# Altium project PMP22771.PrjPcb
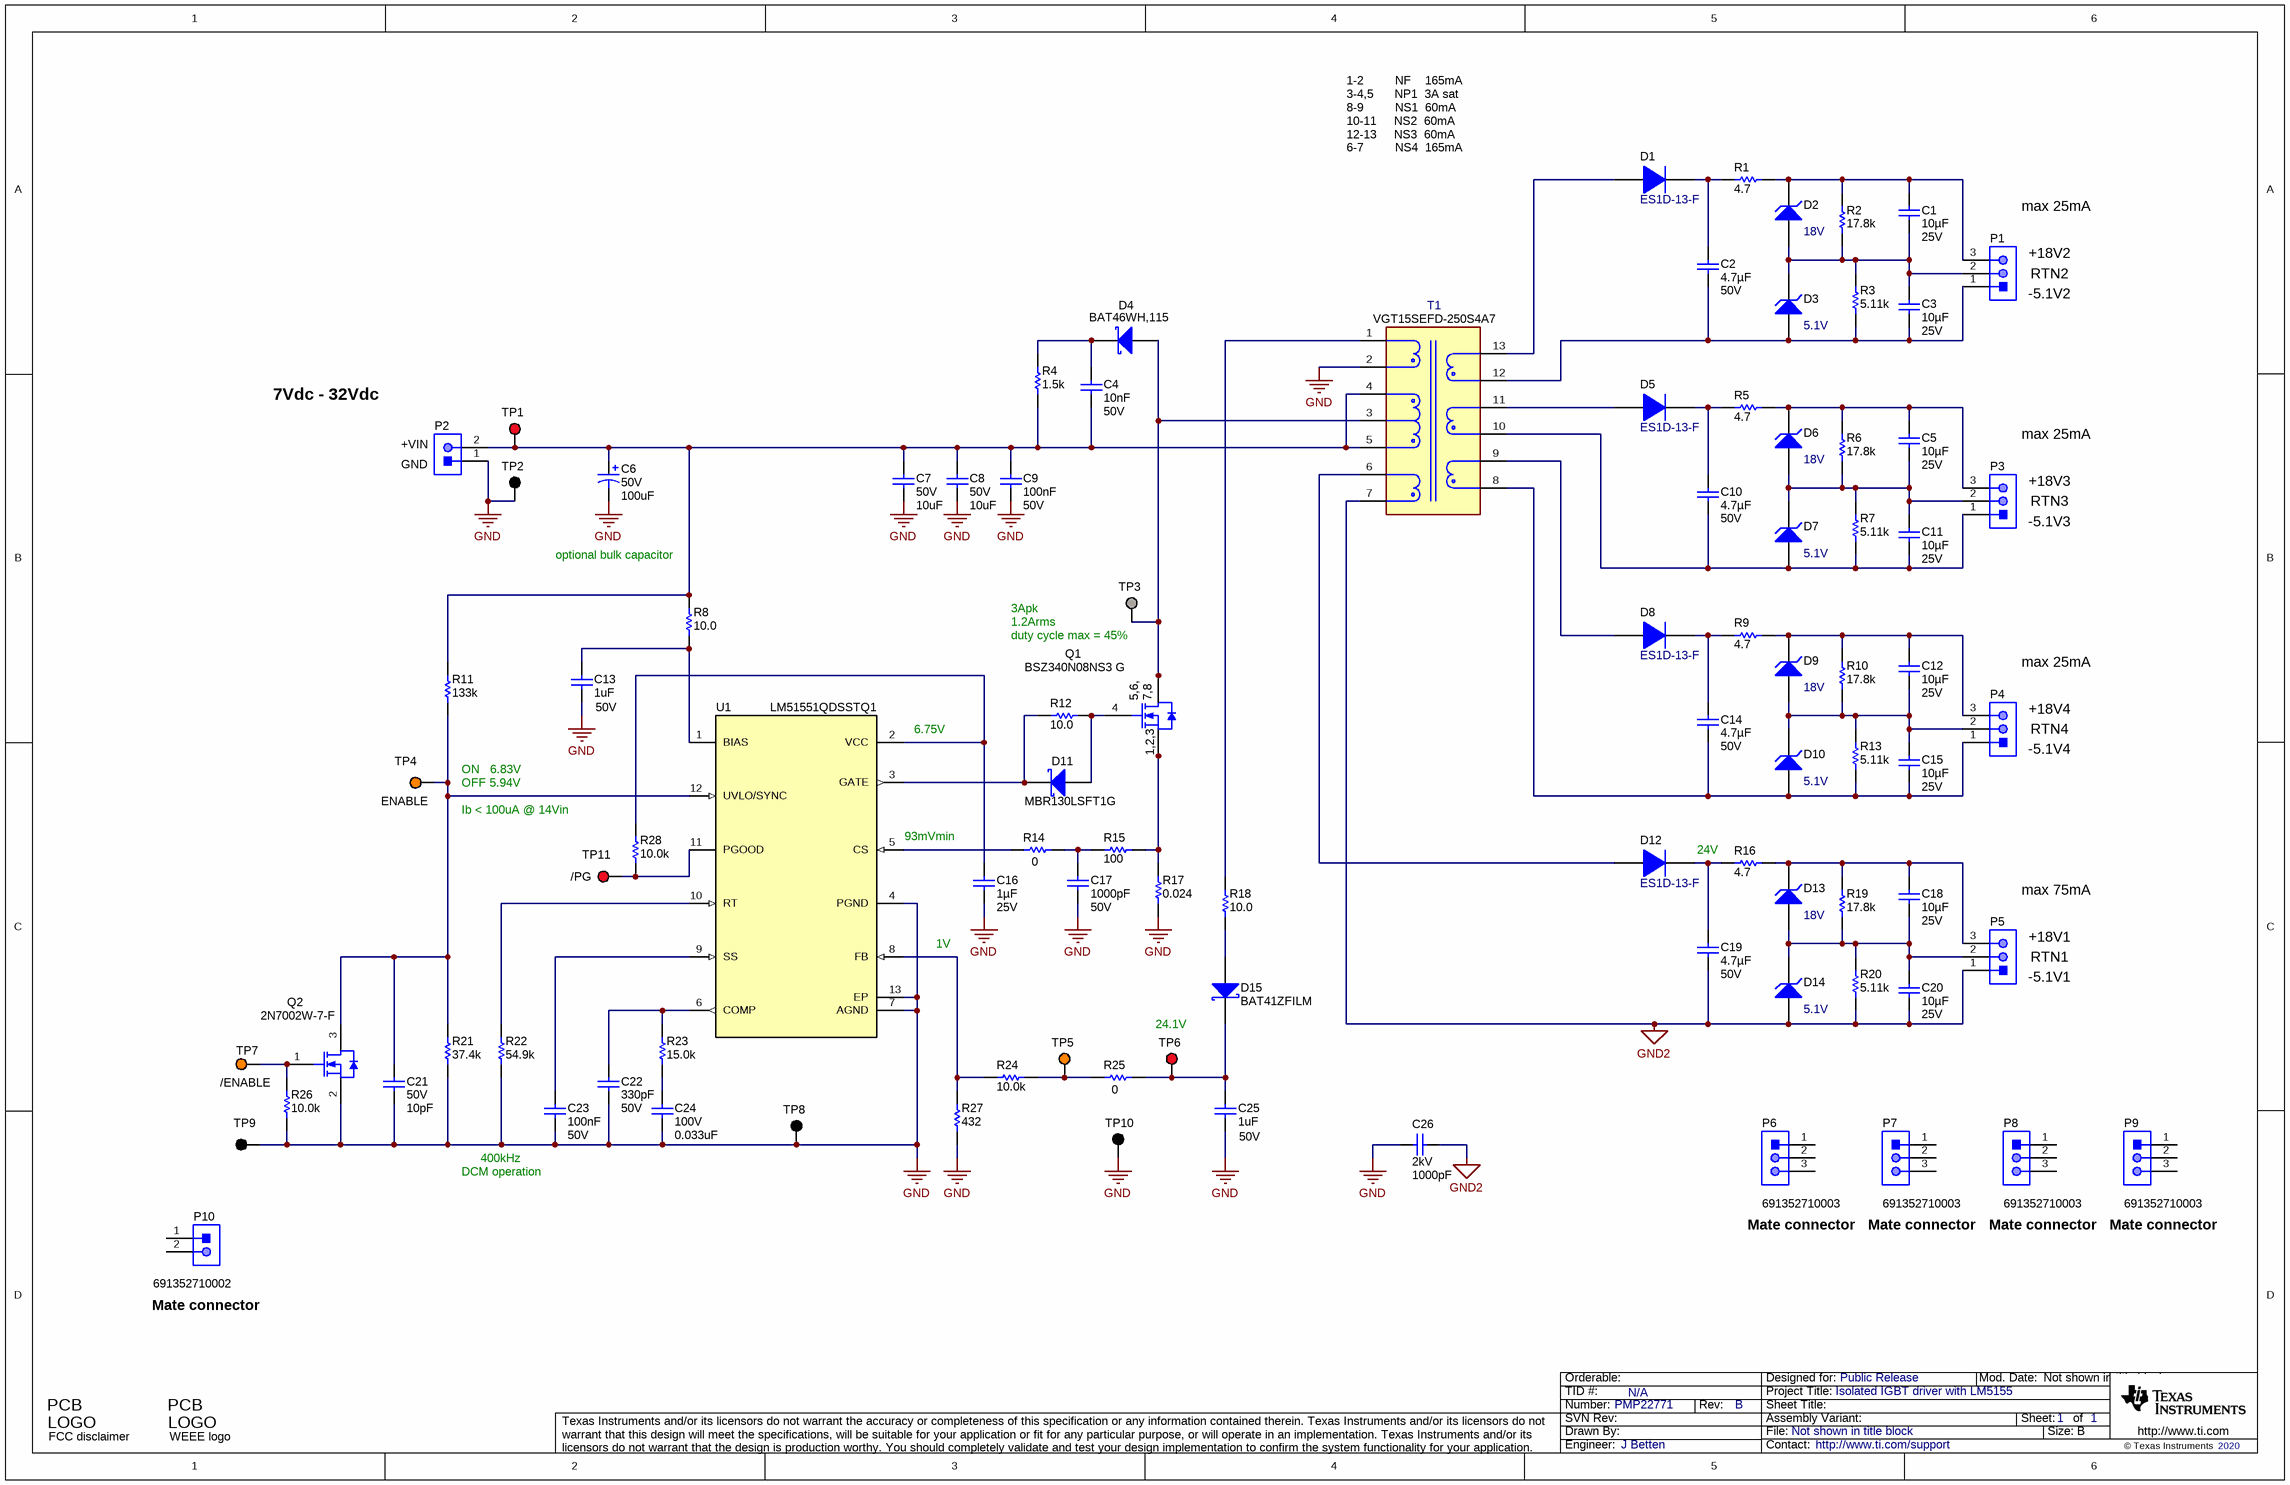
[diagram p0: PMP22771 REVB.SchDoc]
TID: N/A; TechSupport: http://www.ti.com/support; SCH_Rev: B; PRJ_Title: Isolated IGBT driver with LM5155; PRJ_Number: PMP22771; PRJ_Engineer: J Betten; PRJ_Customer: Public Release; PCB_Rev: A; PCB_Layout: J Betten; CopyrightYear: 2020
1 sheet, 96 parts. Net scope: global (net labels, ports and power ports of the same name join across sheets).
Board file: PMP22771 REVA.PcbDoc

## Sheet PMP22771 REVB.SchDoc
size 431 x 279 mm; Date: Not shown in title block; ApprovedBy: Not shown in title block; CheckedBy: Not shown in title block; Author: Not shown in title block; CompanyName: Not shown in title block; Engineer: Not shown in title block; Organization: Not shown in title block; Address1: Not shown in title block; Address2: Not shown in title block; Address3: Not shown in title block; Address4: Not shown in title block; DocumentNumber: 1; Revision: Use project parameter SCH_Rev; SheetNumber: 1; SheetTotal: 1; PageSetup: Record=PageOptions¦CenterHorizontal=True¦CenterVertical=True¦PrintScale=1.00¦XCorrection=1.00¦YCorrection=1.00¦PrintKind=0¦BorderSize=5000000¦LeftOffset=0¦BottomOffset=0¦Orientation=2¦PaperLength=1000¦PaperWidth=1000¦Scale=100¦PaperSource=15¦PrintQuality=600¦MediaType=1¦DitherType=10¦PaperKind=Letter¦PrintScaleMode=1

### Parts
C1  ValueDisplayed: 10µF  VDC_V: 25V  [1206_190]  (hidden comment: CGA5L1X7R1E106K160AE)
C2  ValueDisplayed: 4.7µF  VDC_V: 50V  [1206_190]  (hidden comment: CGA5L3X7R1H475K160AE)
C3  ValueDisplayed: 10µF  VDC_V: 25V  [1206_190]  (hidden comment: CGA5L1X7R1E106K160AE)
C4  Cap_F: 10nF  VDC_V: 50V  [0603]  (hidden comment: GCM188R71H103KA37D)
C5  ValueDisplayed: 10µF  VDC_V: 25V  [1206_190]  (hidden comment: CGA5L1X7R1E106K160AE)
C6  VDC_V: 50V  ValueDisplayed: 100uF  [SM_RADIAL_10BMM]  (hidden comment: EEHZC1H101P)
C7  VDC_V: 50V  ValueDisplayed: 10uF  [1210_270]  (hidden comment: GRM32ER71H106KA12L)
C8  VDC_V: 50V  ValueDisplayed: 10uF  [1210_270]  (hidden comment: GRM32ER71H106KA12L)
C9  Cap_F: 100nF  VDC_V: 50V  [0603]  (hidden comment: GCM188R71H104KA57D)
C10  ValueDisplayed: 4.7µF  VDC_V: 50V  [1206_190]  (hidden comment: CGA5L3X7R1H475K160AE)
C11  ValueDisplayed: 10µF  VDC_V: 25V  [1206_190]  (hidden comment: CGA5L1X7R1E106K160AE)
C12  ValueDisplayed: 10µF  VDC_V: 25V  [1206_190]  (hidden comment: CGA5L1X7R1E106K160AE)
C13  ValueDisplayed: 1uF  Value2: 50V  [0805_HV]  (hidden comment: Capacitor)
C14  ValueDisplayed: 4.7µF  VDC_V: 50V  [1206_190]  (hidden comment: CGA5L3X7R1H475K160AE)
C15  ValueDisplayed: 10µF  VDC_V: 25V  [1206_190]  (hidden comment: CGA5L1X7R1E106K160AE)
C16  Cap_F: 1µF  VDC_V: 25V  [0603]  (hidden comment: GCM188R71E105KA64D)
C17  ValueDisplayed: 1000pF  VDC_V: 50V  [0603]  (hidden comment: GCM1885C1H102JA16D)
C18  ValueDisplayed: 10µF  VDC_V: 25V  [1206_190]  (hidden comment: CGA5L1X7R1E106K160AE)
C19  ValueDisplayed: 4.7µF  VDC_V: 50V  [1206_190]  (hidden comment: CGA5L3X7R1H475K160AE)
C20  ValueDisplayed: 10µF  VDC_V: 25V  [1206_190]  (hidden comment: CGA5L1X7R1E106K160AE)
C21  VDC_V: 50V  ValueDisplayed: 10pF  [0603]  (hidden comment: GRM1885C1H100JA01D)
C22  Cap_F: 330pF  VDC_V: 50V  [0603]  (hidden comment: GRM188R71H331KA01D)
C23  Cap_F: 100nF  VDC_V: 50V  [0603]  (hidden comment: CGA3E2X7R1H104K080AA)
C24  VDC_V: 100V  ValueDisplayed: 0.033uF  [0603]  (hidden comment: CGA3E3X7S2A333K080AB)
C25  ValueDisplayed: 1uF  Value2: 50V  [0805_HV]  (hidden comment: Capacitor)
C26  VDC_V: 2kV  ValueDisplayed: 1000pF  [1206_180]  (hidden comment: C1206C102KGRACAUTO)
D1  ES1D-13-F  [SMA]
D2  value 18V  [SOD-123]  (hidden comment: Zener)
D3  value 5.1V  [SOD-123]  (hidden comment: Zener)
D4  PartNumber: BAT46WH,115  [SOD-123F]  (hidden comment: DIODE_SCHOTTKY)
D5  ES1D-13-F  [SMA]
D6  value 18V  [SOD-123]  (hidden comment: Zener)
D7  value 5.1V  [SOD-123]  (hidden comment: Zener)
D8  ES1D-13-F  [SMA]
D9  value 18V  [SOD-123]  (hidden comment: Zener)
D10  value 5.1V  [SOD-123]  (hidden comment: Zener)
D11  MBR130LSFT1G  [SOD-123FL]
D12  ES1D-13-F  [SMA]
D13  value 18V  [SOD-123]  (hidden comment: Zener)
D14  value 5.1V  [SOD-123]  (hidden comment: Zener)
D15  BAT41ZFILM  [SOD-123]
Logo1  FCC disclaimer  [FCC_disclaimer]  (no BOM)
Logo2  WEEE logo  [WEEE_Minimum]  (no BOM)
P1  691313710003  [691313710003]  (value not drawn)
P2  691313710002  [691313710002]  (value not drawn)
P3  691313710003  [691313710003]  (value not drawn)
P4  691313710003  [691313710003]  (value not drawn)
P5  691313710003  [691313710003]  (value not drawn)
P6  691352710003  [691313710003]
P7  691352710003  [691313710003]
P8  691352710003  [691313710003]
P9  691352710003  [691313710003]
P10  691352710002  [691313710002]
Q1  PartNumber: BSZ340N08NS3 G  [PG-TSDSON-8]  (hidden comment: MOSFET_N_D56789G4S123)
Q2  2N7002W-7-F  [SOT-323]
R1  ValueDisplayed: 4.7  [1206]  (hidden comment: CRCW12064R70JNEAHP)
R2  ValueDisplayed: 17.8k  [0805_HV]  (hidden comment: Resistor)
R3  ValueDisplayed: 5.11k  [0805_HV]  (hidden comment: Resistor)
R4  ValueDisplayed: 1.5k  [1206]  (hidden comment: CRCW12061K50JNEA)
R5  ValueDisplayed: 4.7  [1206]  (hidden comment: CRCW12064R70JNEAHP)
R6  ValueDisplayed: 17.8k  [0805_HV]  (hidden comment: Resistor)
R7  ValueDisplayed: 5.11k  [0805_HV]  (hidden comment: Resistor)
R8  ValueDisplayed: 10.0  [0603]  (hidden comment: Resistor)
R9  ValueDisplayed: 4.7  [1206]  (hidden comment: CRCW12064R70JNEAHP)
R10  ValueDisplayed: 17.8k  [0805_HV]  (hidden comment: Resistor)
R11  ValueDisplayed: 133k  [0603]  (hidden comment: CRCW0603133KFKEA)
R12  ValueDisplayed: 10.0  [0603]  (hidden comment: Resistor)
R13  ValueDisplayed: 5.11k  [0805_HV]  (hidden comment: Resistor)
R14  ValueDisplayed: 0  [0603]  (hidden comment: Resistor)
R15  ValueDisplayed: 100  [0603]  (hidden comment: Resistor)
R16  ValueDisplayed: 4.7  [1206]  (hidden comment: CRCW12064R70JNEAHP)
R17  ValueDisplayed: 0.024  [1206]  (hidden comment: ERJ-8CWFR024V)
R18  ValueDisplayed: 10.0  [0805_HV]  (hidden comment: CRCW080510R0FKEA)
R19  ValueDisplayed: 17.8k  [0805_HV]  (hidden comment: Resistor)
R20  ValueDisplayed: 5.11k  [0805_HV]  (hidden comment: Resistor)
R21  ValueDisplayed: 37.4k  [0603]  (hidden comment: CRCW060337K4FKEA)
R22  ValueDisplayed: 54.9k  [0603]  (hidden comment: CRCW060354K9FKEA)
R23  ValueDisplayed: 15.0k  [0603]  (hidden comment: CRCW060315K0FKEA)
R24  ValueDisplayed: 10.0k  [0805_HV]  (hidden comment: Resistor)
R25  ValueDisplayed: 0  [0603]  (hidden comment: Resistor)
R26  ValueDisplayed: 10.0k  [0603]  (hidden comment: CRCW060310K0FKEA)
R27  ValueDisplayed: 432  [0603]  (hidden comment: Resistor)
R28  ValueDisplayed: 10.0k  [0603]  (hidden comment: CRCW060310K0FKEA)
T1  VGT15SEFD-250S4A7  [FP-VGT15SEFD-250S4A7_SMT_TRANSFORMER_23MM0_15MM4-MFG]
TP1  5000  [Keystone5000]  (value not drawn)
TP2  5001  [Keystone5001]  (value not drawn)
TP3  RCU-0C  [TE_RCU]  (value not drawn)
TP4  ENABLE  [Keystone5003]
TP5  5003  [Keystone5003]  (value not drawn)
TP6  5000  [Keystone5000]  (value not drawn)
TP7  /ENABLE  [Keystone5003]
TP8  5001  [Keystone5001]  (value not drawn)
TP9  5001  [Keystone5001]  (value not drawn)
TP10  5001  [Keystone5001]  (value not drawn)
TP11  5000  [Keystone5000]  (value not drawn)
U1  LM51551QDSSTQ1  [DSS0012C]

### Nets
GND: C6.2(-) C7.2 C8.2 C9.2 C13.2 C16.2 C17.2 C21.2 C22.2 C23.2 C24.2 C25.2 C26.2 P2.1 Q2.2(S) R17.1 R21.1 R22.1 R26.1 R27.1 T1.2 TP2.1 TP8.1 TP9.1 TP10.1 U1.4(PGND) U1.7(AGND) U1.13(EP)
GND2: C19.2 C20.2 C26.1 D14.2(A) P5.1 R20.1 T1.7
NetC1_1: C1.1 D2.1(K) P1.3 R1.2 R2.2
NetC1_2: C1.2 C3.1 D2.2(A) D3.1(K) P1.2 R2.1 R3.2
NetC2_1: C2.1 D1.1(K) R1.1
NetC2_2: C2.2 C3.2 D3.2(A) P1.1 R3.1 T1.12
NetC4_1: C4.1 C6.1(+) C7.1 C8.1 C9.1 P2.2 R4.2 R8.2 R11.2 T1.4 T1.5 TP1.1
NetC4_2: C4.2 D4.1(K) R4.1
NetC5_1: C5.1 D6.1(K) P3.3 R5.2 R6.2
NetC5_2: C5.2 C11.1 D6.2(A) D7.1(K) P3.2 R6.1 R7.2
NetC10_1: C10.1 D5.1(K) R5.1
NetC10_2: C10.2 C11.2 D7.2(A) P3.1 R7.1 T1.10
NetC12_1: C12.1 D9.1(K) P4.3 R9.2 R10.2
NetC12_2: C12.2 C15.1 D9.2(A) D10.1(K) P4.2 R10.1 R13.2
NetC13_1: C13.1 R8.1 U1.1(BIAS)
NetC14_1: C14.1 D8.1(K) R9.1
NetC14_2: C14.2 C15.2 D10.2(A) P4.1 R13.1 T1.8
NetC16_1: C16.1 R28.2 U1.2(VCC)
NetC17_1: C17.1 R14.2 R15.1
NetC18_1: C18.1 D13.1(K) P5.3 R16.2 R19.2
NetC18_2: C18.2 C20.1 D13.2(A) D14.1(K) P5.2 R19.1 R20.2
NetC19_1: C19.1 D12.1(K) R16.1
NetC21_1: C21.1 Q2.3(D) R11.1 R21.2 TP4.1 U1.12(UVLO/SYNC)
NetC22_1: C22.1 R23.2 U1.6(COMP)
NetC23_1: C23.1 U1.9(SS)
NetC24_1: C24.1 R23.1
NetC25_1: C25.1 D15.1(K) R25.2 TP6.1
NetD1_2: D1.2(A) T1.13
NetD4_2: D4.2(A) Q1.5(D) Q1.6(D) Q1.7(D) Q1.8(D) Q1.9(D) T1.3 TP3.1
NetD5_2: D5.2(A) T1.11
NetD8_2: D8.2(A) T1.9
NetD11_1: D11.1(K) R12.1 U1.3(GATE)
NetD11_2: D11.2(A) Q1.4(G) R12.2
NetD12_2: D12.2(A) T1.6
NetD15_2: D15.2(A) R18.1
NetQ1_1: Q1.1(S) Q1.2(S) Q1.3(S) R15.2 R17.2
NetQ2_1: Q2.1(G) R26.2 TP7.1
NetR14_1: R14.1 U1.5(CS)
NetR18_2: R18.2 T1.1
NetR22_2: R22.2 U1.10(RT)
NetR24_1: R24.1 R27.2 U1.8(FB)
NetR24_2: R24.2 R25.1 TP5.1
NetR28_1: R28.1 TP11.1 U1.11(PGOOD)

Not connected (* = marked no-connect by the designer): P6 1 2 3; P7 1 2 3; P8 1 2 3; P9 1 2 3; P10 1 2

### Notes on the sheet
- 1-2         NF    165mA
  3-4,5      NP1  3A sat
  8-9         NS1  60mA
  10-11     NS2  60mA
  12-13     NS3  60mA
  6-7         NS4  165mA
- max 25mA
- (near P1) RTN2
- (near P1) +18V2
- (near P1) -5.1V2
- 7Vdc - 32Vdc
- (near P2) +VIN
- (near P2) GND
- (near P3) RTN3
- (near P3) +18V3
- optional bulk capacitor
- (near P3) -5.1V3
- 3Apk
- 1.2Arms
- (near TP3) duty cycle max = 45%
- (near P4) +18V4
- ON   6.83V
- (near U1) 6.75V
- (near P4) RTN4
- (near P4) -5.1V4
- (near TP4) OFF 5.94V
- Ib < 100uA @ 14Vin
- 93mVmin
- (near TP11) /PG
- 24V
- max 75mA
- 1V
- (near P5) RTN1
- (near P5) +18V1
- (near P5) -5.1V1
- 24.1V
- (near C23) DCM operation
- (near C23) 400kHz
- (near P6) Mate connector
- (near P7) Mate connector
- (near P8) Mate connector
- (near P9) Mate connector
- (near P10) Mate connector
- Labels drawn without touching a wire or pin: PG

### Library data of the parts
C1 C3 C5 C11 C12 C15 C18 C20 = CMP-0085253-1: CAP, CERM, 10 µF, 25 V,+/- 10%, X7R, AEC-Q200 Grade 1, 1206; Manufacturer: TDK; AEC Qualified: Y; Polarized: N; SizeAreaWB_mm2: 10.92; TaMax_C: 125°C; Value: 10uF; AEC Category: Q200; TaMin_C: -55°C; U/M: EA; SizeY_mm: 1.6; SizeArea_mm2: 5.12; AEC Grade: 1; SizeZ_mm: 1.9; Cap_Case: 1206; SizeX_mm: 3.2
C2 C10 C14 C19 = CMP-0085349-1: CAP, CERM, 4.7 µF, 50 V,+/- 10%, X7R, AEC-Q200 Grade 1, 1206; Manufacturer: TDK; Cap_Case: 1206; AEC Category: Q200; SizeY_mm: 1.6; TaMin_C: -55°C; TaMax_C: 125°C; U/M: EA; AEC Qualified: Y; SizeAreaWB_mm2: 10.92; AEC Grade: 1; SizeZ_mm: 1.9; SizeArea_mm2: 5.12; Value: 4.7uF; Polarized: N; SizeX_mm: 3.2
C4 = CMP-0007143-1: CAP, CERM, 0.01 uF, 50 V, +/- 10%, X7R, AEC-Q200 Grade 1, 0603; Manufacturer: MuRata; TaMin_C: -55°C; Polarized: N; SizeAreaWB_mm2: 4.68; Value1: Unknown; U/M: EA; Value: 0.01uF; TaMax_C: 125°C; SizeZ_mm: 1; SizeX_mm: 1.6; SizeY_mm: 0.8; SizeArea_mm2: 1.28; AEC Qualified: Y; AEC Category: Q200
C6 = CMP-0012596-3: CAP, Polymer Hybrid, 100 uF, 50 V, +/- 20%, 28 mohm, 10x10 SMD; Manufacturer: Panasonic; TaMin_C: -55°C; ESR_ohm: 28; Polarized: Y; SizeAreaWB_mm2: 159.9; Value1: 0.028 ohm; Value: 100uF; TaMax_C: 125°C; SizeZ_mm: 10.2; SizeX_mm: 11; SizeY_mm: 10.3; SizeArea_mm2: 113.3; CompType: Capacitor; Cap_F: 100µF; IRMS_A: 1.6A; AEC Category: Q200
C7 C8 = CMP-0009226-3: CAP, CERM, 10 uF, 50 V, +/- 10%, X7R, 1210; Manufacturer: MuRata; TaMin_C: -55°C; Polarized: N; SizeAreaWB_mm2: 14.7; Value1: Unknown; U/M: EA; Value: 10uF; TaMax_C: 125°C; SizeZ_mm: 2.7; SizeX_mm: 3.2; SizeY_mm: 2.5; Cap_Case: 1210; SizeArea_mm2: 8; Cap_F: 10µF; AEC Category: Q200
C9 = CMP-0007144-4: CAP, CERM, 0.1 uF, 50 V, +/- 10%, X7R, 0603; Manufacturer: MuRata; TaMin_C: -55°C; ESR_ohm: 0.02; Polarized: N; SizeAreaWB_mm2: 4.68; Value1: 0.02 ohm; U/M: EA; Value: 0.1uF; TaMax_C: 125°C; SizeZ_mm: 1; SizeX_mm: 1.6; SizeY_mm: 0.8; SizeArea_mm2: 1.28; IRMS_A: 1.84A; AEC Category: Q200
C13 C25 = CMP-0008350-2: CAP, CERM, 1 uF, 50 V, +/- 10%, X7R, 0805; PartNumber: GRM21BR71H105KA12L; Manufacturer: MuRata; Polarized: N; Value: 1uF; U/M: EA; Cap_F: 1µF; Value1: Unknown; TaMin_C: -55°C; TaMax_C: 125°C; Cap_Case: 0805; SizeArea_mm2: 2.5; SizeAreaWB_mm2: 6.75; SizeX_mm: 2; SizeY_mm: 1.25; SizeZ_mm: 1.45; AEC Category: Q200
C16 = CMP-0007139-4: CAP, CERM, 1 uF, 25 V, +/- 10%, X7R, AEC-Q200 Grade 1, 0603; Manufacturer: MuRata; TaMin_C: -55°C; Polarized: N; SizeAreaWB_mm2: 4.68; Value1: Unknown; U/M: EA; Value: 1uF; TaMax_C: 125°C; SizeZ_mm: 1; SizeX_mm: 1.6; SizeY_mm: 0.8; SizeArea_mm2: 1.28; AEC Qualified: Y; AEC Category: Q200
C17 = CMP-0086079-1: CAP, CERM, 1000 pF, 50 V,+/- 5%, C0G/NP0, AEC-Q200 Grade 1, 0603; Manufacturer: MuRata; Value: 1000pF; U/M: EA; Green_Lifecycle: Active; SizeAreaWB_mm2: 4.68; SizeX_mm: 1.6; SizeZ_mm: 1; AEC Qualified: Y; SizeArea_mm2: 1.28; TaMax_C: 125°C; SizeY_mm: 0.8; Cap_F: 1nF; TaMin_C: -55°C; Green_REACh: Incomplete; AEC Category: Q200; Polarized: N
C21 = CMP-0007170-4: CAP, CERM, 10 pF, 50 V, +/- 5%, C0G/NP0, 0603; Manufacturer: MuRata; TaMin_C: -55°C; Polarized: N; SizeAreaWB_mm2: 4.68; Value1: Unknown; U/M: EA; Value: 10pF; TaMax_C: 125°C; SizeZ_mm: 1; SizeX_mm: 1.6; SizeY_mm: 0.8; SizeArea_mm2: 1.28; AEC Category: Q200
C22 = CMP-0007449-4: CAP, CERM, 330 pF, 50 V, +/- 10%, X7R, 0603; Manufacturer: MuRata; TaMin_C: -55°C; Polarized: N; SizeAreaWB_mm2: 4.68; Value1: Unknown; U/M: EA; Value: 330pF; TaMax_C: 125°C; SizeZ_mm: 1; SizeX_mm: 1.6; SizeY_mm: 0.8; SizeArea_mm2: 1.28; AEC Category: Q200
C23 = CMP-0007078-4: CAP, CERM, 0.1 uF, 50 V, +/- 10%, X7R, AEC-Q200 Grade 1, 0603; Manufacturer: TDK; TaMin_C: -55°C; ESR_ohm: 0.0296; Polarized: N; SizeAreaWB_mm2: 4.68; Value1: 0.0296 ohm; U/M: EA; Value: 0.1uF; TaMax_C: 125°C; SizeZ_mm: 1; SizeX_mm: 1.6; SizeY_mm: 0.8; SizeArea_mm2: 1.28; AEC Qualified: Y; IRMS_A: 971.99mA; AEC Category: Q200
C24 = CMP-0007100-4: CAP, CERM, 0.033 uF, 100 V, +/- 10%, X7S, AEC-Q200 Grade 1, 0603; Manufacturer: TDK; TaMin_C: -55°C; ESR_ohm: 0.139637; Polarized: N; SizeAreaWB_mm2: 4.68; Value1: 0.139637 ohm; U/M: EA; TaMax_C: 125°C; SizeZ_mm: 1; SizeX_mm: 1.6; SizeY_mm: 0.8; SizeArea_mm2: 1.28; AEC Qualified: Y; Cap_F: 33nF; IRMS_A: 462.257mA; AEC Category: Q200
C26 = CMP-0008579-2: CAP, CERM, 1000 pF, 2000 V, +/- 10%, X7R, AEC-Q200 Grade 1, 1206; Manufacturer: Kemet; TaMin_C: -55°C; Polarized: N; SizeAreaWB_mm2: 10.92; Value1: Unknown; U/M: EA; Value: 1000pF; TaMax_C: 125°C; SizeZ_mm: 1.8; SizeX_mm: 3.2; SizeY_mm: 1.6; Cap_Case: 1206; Value2: 2000V; SizeArea_mm2: 5.12; AEC Qualified: Y; Cap_F: 1nF; AEC Grade: 1; AEC Category: Q200
D1 D5 D8 D12 = CMP-0029024-2: Diode, Ultrafast, 200 V, 1 A, SMA; Manufacturer: Diodes Inc.; Value2: 0.92V; Green_Lifecycle: Active; Io_A: 1A; Vf_V: 920mV; Value: 200V; SizeX_mm: 5.59; AEC Category: Q101; TJmax_C: 150°C; SizeAreaWB_mm2: 37.3428; SizeArea_mm2: 16.3228; RJC_CperW: 25; SizeZ_mm: 2.87; Green_REACh: Passed; SizeY_mm: 2.92
D2 D6 D9 D13 = CMP-0005755-4: Diode, Zener, 18 V, 500 mW, SOD-123; PartNumber: MMSZ5248B-7-F; Manufacturer: Diodes Inc.; Power_W: 500mW; Value1: 0.5W; RJA_CperW: 350; SizeAreaWB_mm2: 13.095; SizeArea_mm2: 6.545; SizeX_mm: 3.85; SizeY_mm: 1.7; SizeZ_mm: 1.35; AEC Category: Q101
D3 D7 D10 D14 = CMP-0005802-3: Diode, Zener, 5.1 V, 500 mW, SOD-123; PartNumber: MMSZ5231B-7-F; Manufacturer: Diodes Inc.; Power_W: 500mW; Value1: 0.5W; RJA_CperW: 350; SizeAreaWB_mm2: 13.095; SizeArea_mm2: 6.545; SizeX_mm: 3.85; SizeY_mm: 1.7; SizeZ_mm: 1.35; AEC Category: Q101
D4 = CMP-0028632-2: Diode, Schottky, 100 V, 0.25 A, SOD-123F; Manufacturer: Nexperia; Vf_V: 850mV; Value: 100V; Value1: 0.25A; Value2: 0.85V; Io_A: 250mA; TJmax_C: 150°C; SizeAreaWB_mm2: 11.7; SizeArea_mm2: 5.6; SizeX_mm: 3.5; SizeY_mm: 1.6; SizeZ_mm: 1.1; AEC Category: Q101; Green_Lifecycle: Not Set; Green_REACh: Incomplete
D11 = CMP-0028889-2: Diode, Schottky, 30 V, 1 A, AEC-Q101, SOD-123FL; Manufacturer: ON Semiconductor; Value1: 1A; SizeArea_mm2: 5.94; SizeAreaWB_mm2: 12.19; Green_REACh: Passed; Vr_V: 30V; Green_Lifecycle: Active; AEC Category: Q101; AEC Qualified: Y; Vf_V: 380mV; SizeZ_mm: 0.98; Value2: 0.38V; SizeX_mm: 3.6; Value: 30V; TJmax_C: 125°C; SizeY_mm: 1.65
D15 = CMP-0028445-2: Diode, Schottky, 100 V, 0.2 A, SOD-123; Manufacturer: STMicroelectronics; SizeZ_mm: 1.35; Io_A: 200mA; Value: 100V; Value1: 0.2A; SizeAreaWB_mm2: 13.095; SizeY_mm: 1.7; SizeArea_mm2: 6.545; SizeX_mm: 3.85; Green_REACh: Passed; AEC Category: Q101; Vf_V: 1V; Green_Lifecycle: Active; TJmax_C: 150°C
Logo1 = CMP-0074847-1: FCC_disclaimer; Library Reference: Logo
Logo2 = CMP-0074769-1
P1 P3-P5 = CMP-1502-02049-1: Serie 3137 - 5.00mm Close Horizontal PCB Header WR-TBL, 3 pin; Manufacturer: Wurth Elektronik; Gender: Male; PinNumber: 3
P2 = CMP-1502-02048-1: Serie 3137 - 5.00mm Close Horizontal PCB Header WR-TBL, 2 pin; Manufacturer: Wurth Elektronik; Gender: Male; PinNumber: 2
P6-P9 = CMP-1502-02049-1: 3 Position Terminal Block Plug, Female Sockets 0.197" (5.00mm); Manufacturer: Wurth Elektronik; Gender: Male; PinNumber: 3
P10 = CMP-1502-02048-1: 2 Position Terminal Block Plug, Female Sockets 0.197" (5.00mm); Manufacturer: Wurth Elektronik; Gender: Male; PinNumber: 2
Q1 = CMP-0000911-1: MOSFET, N-CH, 80 V, 23 A, PG-TSDSON-8; Manufacturer: Infineon Technologies; Alternate Manufacturer: None; U/M: EA; ChType: N; Value: 80V; Value2: 6.8 nC; QgTyp_nC: 6.8; Vgs_V: 20V; IdsMax_A: 23A; SizeAreaWB_mm2: 19.36; SizeArea_mm2: 11.56; SizeX_mm: 3.4; SizeZ_mm: 1.1; AEC Category: Q101
Q2 = CMP-0000776-1: MOSFET, N-CH, 60 V, 0.115 A, SOT-323; Alternate Manufacturer: None; Manufacturer: Diodes Inc.; SizeZ_mm: 1.1; ChType: N; Value1: 7; VdsMax_V: 60V; SizeX_mm: 2.2; Vgs_V: 20V; Value: 60V; Rdson45_ohm: 7.5; SizeArea_mm2: 4.84; AEC Category: Q101; IdsMax_A: 115mA; SizeAreaWB_mm2: 10.24; U/M: EA
R1 R5 R9 R16 = CMP-0018694-3: RES, 4.7, 5%, 0.75 W, AEC-Q200 Grade 0, 1206; Manufacturer: Vishay-Dale; Power_W: 750mW; TempCo: 200 ppm/C; Value_Code: 4R70; Value: 4.7; EIA_Code: E24; SizeX_mm: 3.2; SizeY_mm: 1.6; SizeZ_mm: 1.35; Value2: 0.75W; SizeArea_mm2: 5.12; AEC Qualified: Y; AEC Grade: 0; AEC Category: Q200
R2 R6 R10 R19 = CMP-0020932-3: RES, 17.8 k, 1%, 0.125 W, AEC-Q200 Grade 0, 0805; PartNumber: CRCW080517K8FKEA; Manufacturer: Vishay-Dale; Value: 17.8k; Value_Code: 17k8; Power_W: 125mW; Value2: 0.125W; VDC_V: 150V; TempCo: 100 ppm/C; SizeArea_mm2: 2.5; SizeX_mm: 2; SizeY_mm: 1.25; SizeZ_mm: 1.45; EIA_Code: E96; AEC Category: Q200; AEC Qualified: Y; AEC Grade: 0
R3 R7 R13 R20 = CMP-0021344-3: RES, 5.11 k, 1%, 0.125 W, AEC-Q200 Grade 0, 0805; PartNumber: CRCW08055K11FKEA; Manufacturer: Vishay-Dale; Value: 5.11k; Value_Code: 5k11; Power_W: 125mW; Value2: 0.125W; VDC_V: 150V; TempCo: 100 ppm/C; SizeArea_mm2: 2.5; SizeX_mm: 2; SizeY_mm: 1.25; SizeZ_mm: 1.45; EIA_Code: E96; AEC Category: Q200; AEC Qualified: Y; AEC Grade: 0
R4 = CMP-0018607-3: RES, 1.5 k, 5%, 0.25 W, AEC-Q200 Grade 0, 1206; Manufacturer: Vishay-Dale; Power_W: 250mW; TempCo: 200 ppm/C; Value_Code: 1k50; Value: 1.5k; EIA_Code: E24; SizeX_mm: 3.2; SizeY_mm: 1.6; SizeZ_mm: 1.35; Value2: 0.25W; SizeArea_mm2: 5.12; AEC Qualified: Y; VDC_V: 200V; AEC Category: Q200; AEC Grade: 0
R8 R12 = CMP-0022003-4: RES, 10.0, 1%, 0.1 W, AEC-Q200 Grade 0, 0603; PartNumber: CRCW060310R0FKEA; Manufacturer: Vishay-Dale; Value: 10.0; Res_ohm: 10; Value_Code: 10R0; Power_W: 100mW; Value2: 0.1W; VDC_V: 75V; TempCo: 100 ppm/C; SizeArea_mm2: 1.28; SizeX_mm: 1.6; SizeY_mm: 0.8; SizeZ_mm: 1; EIA_Code: E96; AEC Category: Q200; AEC Qualified: Y; AEC Grade: 0
R11 = CMP-0022038-4: RES, 133 k, 1%, 0.1 W, AEC-Q200 Grade 0, 0603; Manufacturer: Vishay-Dale; Power_W: 100mW; TempCo: 100 ppm/C; Value: 133k; EIA_Code: E96; SizeX_mm: 1.6; SizeY_mm: 0.8; SizeZ_mm: 1; Value2: 0.1W; SizeArea_mm2: 1.28; AEC Qualified: Y; VDC_V: 75V; AEC Category: Q200; AEC Grade: 0
R14 R25 = CMP-0025697-4: RES, 0, 5%, 0.1 W, AEC-Q200 Grade 0, 0603; PartNumber: CRCW06030000Z0EA; Manufacturer: Vishay-Dale; Value: 0; Value_Code: 0000; Power_W: 100mW; Value2: 0.1W; VDC_V: 75V; TempCo: 200 ppm/C; SizeArea_mm2: 1.28; SizeX_mm: 1.6; SizeY_mm: 0.8; SizeZ_mm: 1; EIA_Code: E24; AEC Category: Q200; AEC Qualified: Y
R15 = CMP-0021991-4: RES, 100, 1%, 0.1 W, AEC-Q200 Grade 0, 0603; PartNumber: CRCW0603100RFKEA; Manufacturer: Vishay-Dale; Value: 100; Value_Code: 100R; Power_W: 100mW; Value2: 0.1W; VDC_V: 75V; TempCo: 100 ppm/C; SizeArea_mm2: 1.28; SizeX_mm: 1.6; SizeY_mm: 0.8; SizeZ_mm: 1; EIA_Code: E96; AEC Category: Q200; AEC Qualified: Y; AEC Grade: 0
R17 = CMP-0750151-1: RES, 0.024, 1%, 1 W, AEC-Q200 Grade 0, 1206; Manufacturer: Panasonic; SizeZ_mm: 1.35; Value2: 1W; AEC Category: Q200; Value: 0.024; SizeAreaWB_mm2: 10.92; TempCo: 200 ppm/C; SizeY_mm: 1.6; SizeArea_mm2: 5.12; SizeX_mm: 3.2; AEC Grade: 0; EIA_Code: E96; AEC Qualified: Y
R18 = CMP-0020847-3: RES, 10.0, 1%, 0.125 W, AEC-Q200 Grade 0, 0805; Manufacturer: Vishay-Dale; Power_W: 125mW; TempCo: 100 ppm/C; Value_Code: 10R0; Value: 10.0; EIA_Code: E96; Res_ohm: 10; SizeX_mm: 2; SizeY_mm: 1.25; SizeZ_mm: 1.45; Value2: 0.125W; SizeArea_mm2: 2.5; AEC Qualified: Y; VDC_V: 150V; AEC Category: Q200; AEC Grade: 0
R21 = CMP-0022360-4: RES, 37.4 k, 1%, 0.1 W, AEC-Q200 Grade 0, 0603; Manufacturer: Vishay-Dale; Power_W: 100mW; TempCo: 100 ppm/C; Value_Code: 37k4; Value: 37.4k; EIA_Code: E96; SizeX_mm: 1.6; SizeY_mm: 0.8; SizeZ_mm: 1; Value2: 0.1W; SizeArea_mm2: 1.28; AEC Qualified: Y; VDC_V: 75V; AEC Category: Q200; AEC Grade: 0
R22 = CMP-0022494-4: RES, 54.9 k, 1%, 0.1 W, AEC-Q200 Grade 0, 0603; Manufacturer: Vishay-Dale; Power_W: 100mW; TempCo: 100 ppm/C; Value_Code: 54k9; Value: 54.9k; EIA_Code: E96; SizeX_mm: 1.6; SizeY_mm: 0.8; SizeZ_mm: 1; Value2: 0.1W; SizeArea_mm2: 1.28; AEC Qualified: Y; VDC_V: 75V; AEC Category: Q200; AEC Grade: 0
R23 = CMP-0022066-4: RES, 15.0 k, 1%, 0.1 W, AEC-Q200 Grade 0, 0603; Manufacturer: Vishay-Dale; Power_W: 100mW; TempCo: 100 ppm/C; Value_Code: 15k0; Value: 15.0k; EIA_Code: E96; Res_ohm: 15k; SizeX_mm: 1.6; SizeY_mm: 0.8; SizeZ_mm: 1; Value2: 0.1W; SizeArea_mm2: 1.28; AEC Qualified: Y; VDC_V: 75V; AEC Category: Q200; AEC Grade: 0
R24 = CMP-0020842-3: RES, 10.0 k, 1%, 0.125 W, AEC-Q200 Grade 0, 0805; PartNumber: CRCW080510K0FKEA; Manufacturer: Vishay-Dale; Value: 10.0k; Res_ohm: 10k; Value_Code: 10k0; Power_W: 125mW; Value2: 0.125W; VDC_V: 150V; TempCo: 100 ppm/C; SizeArea_mm2: 2.5; SizeX_mm: 2; SizeY_mm: 1.25; SizeZ_mm: 1.45; EIA_Code: E96; AEC Category: Q200; AEC Qualified: Y; AEC Grade: 0
R26 R28 = CMP-0021998-4: RES, 10.0 k, 1%, 0.1 W, AEC-Q200 Grade 0, 0603; Manufacturer: Vishay-Dale; Power_W: 100mW; TempCo: 100 ppm/C; Value_Code: 10k0; Value: 10.0k; EIA_Code: E96; Res_ohm: 10k; SizeX_mm: 1.6; SizeY_mm: 0.8; SizeZ_mm: 1; Value2: 0.1W; SizeArea_mm2: 1.28; AEC Qualified: Y; VDC_V: 75V; AEC Category: Q200; AEC Grade: 0
R27 = CMP-0022421-5: RES, 432, 1%, 0.1 W, AEC-Q200 Grade 0, 0603; PartNumber: CRCW0603432RFKEA; Manufacturer: Vishay-Dale; Value: 432; Value_Code: 432R; Power_W: 100mW; Value2: 0.1W; VDC_V: 75V; TempCo: 100 ppm/C; SizeArea_mm2: 1.28; SizeX_mm: 1.6; SizeY_mm: 0.8; SizeZ_mm: 1; EIA_Code: E96; AEC Category: Q200; AEC Qualified: Y; AEC Grade: 0
T1 = CMP-0090899-1: Flyback Converters For For AC/DC Converters SMPS Transformer 2600Vrms Isolation  Surface Mount; Manufacturer: TDK; Voltage_Isolation_Vrms: 2.6kVrms; AEC Grade: Grade 1; AEC Qualified: Yes; SizeZ_mm: 12mm; Ns1toNp: 1:3:3:3:3:3; Ind_H: 2.6µH
TP1 TP6 TP11 = CMP-0055137-1: Test Point, Miniature, Red, TH; Manufacturer: Keystone; CNHeader: FALSE; ContactFinish: Silver; CT: TRUE; Green_Lifecycle: Active; Green_REACh: Passed
TP2 TP8-TP10 = CMP-0055138-1: Test Point, Miniature, Black, TH; Manufacturer: Keystone; CNHeader: FALSE; ContactFinish: Silver; CT: TRUE; Green_Lifecycle: Active; Green_REACh: Passed
TP3 = CMP-0067620-1: PC Test Point, SMT; Manufacturer: TE Connectivity
TP4 TP7 = CMP-0055140-1: Test Point, Miniature, Orange, TH; Manufacturer: Keystone; CNHeader: FALSE; Green_Lifecycle: Active; Green_REACh: Passed; ContactFinish: Silver; CT: TRUE
TP5 = CMP-0055140-1: Test Point, Miniature, Orange, TH; Manufacturer: Keystone; ContactFinish: Silver; CNHeader: FALSE; CT: TRUE; Green_Lifecycle: Active; Green_REACh: Passed
U1 = CMP-0081540-1: Automotive Grade 2.2-MHz Wide Input Non-synchronous Boost Controller, DSS0012C (WSON-12); Alternate PartNumber: LM51551QDSSRQ1; Alternate Manufacturer: Texas Instruments; SizeAreaWB_mm2: 12; SizeZ_mm: 0.8; SizeX_mm: 2; SizeY_mm: 3; SizeArea_mm2: 6; CompType: IC; AEC Qualified: Y; AEC Category: Q200

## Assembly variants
001: not fitted Q2 R26 R? TP7 TP?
